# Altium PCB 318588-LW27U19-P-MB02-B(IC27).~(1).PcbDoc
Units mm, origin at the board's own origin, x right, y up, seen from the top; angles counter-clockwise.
Board outline 187.83 x 97.54 mm, 2 copper layers (Top Layer, Bottom Layer); 79 components, 53 nets, 224 pads, 27 vias.
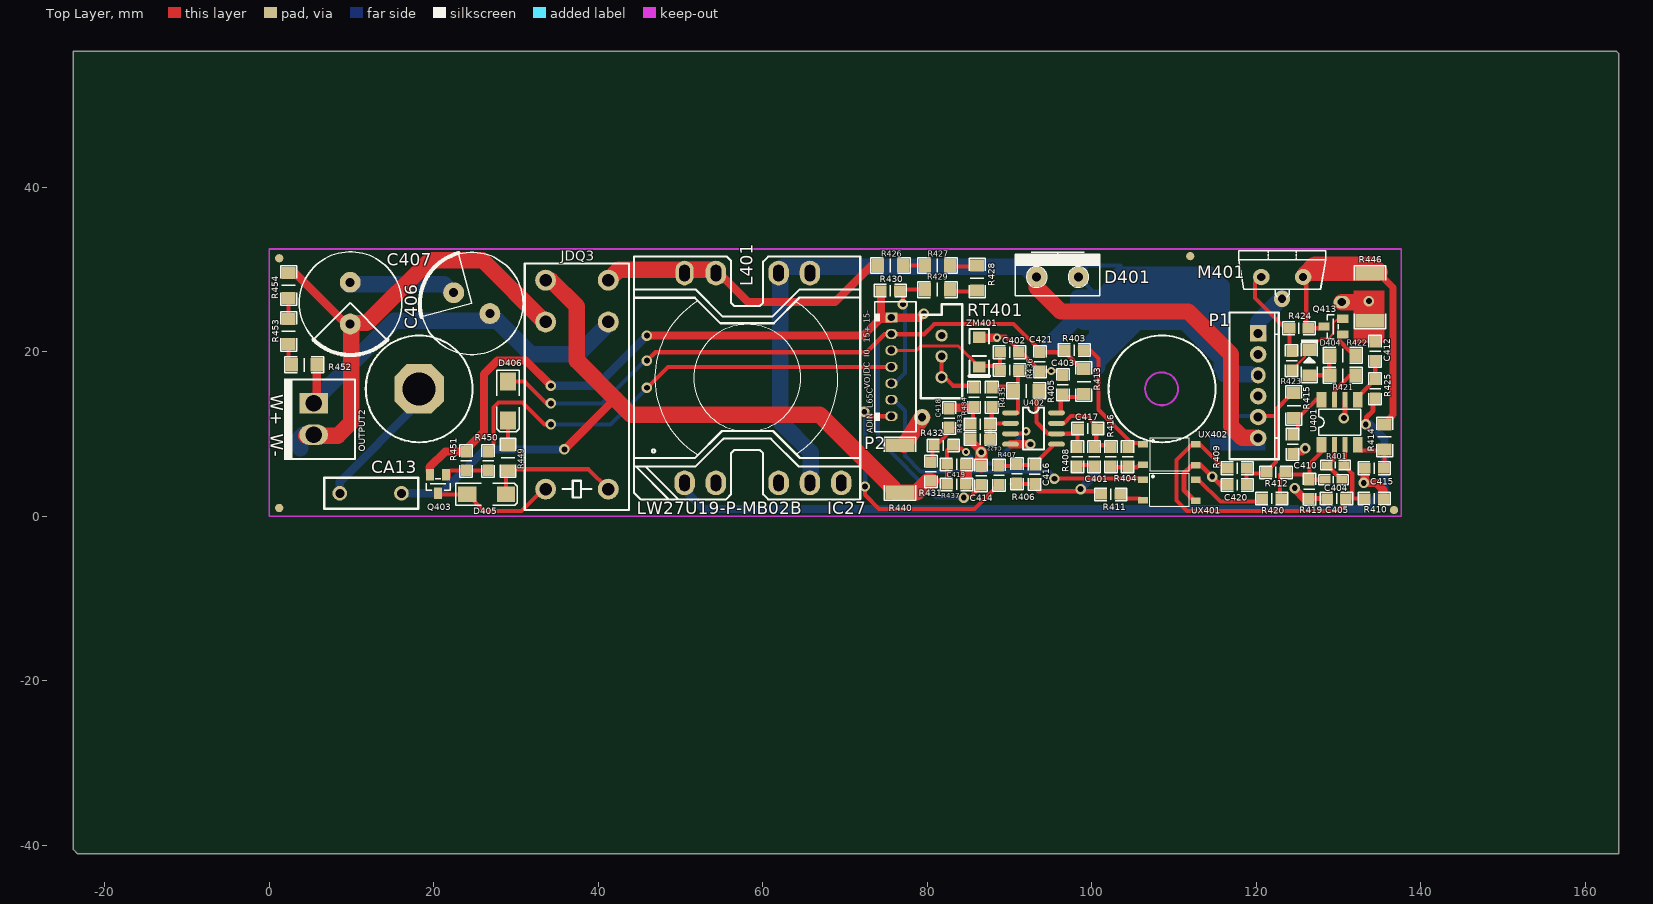
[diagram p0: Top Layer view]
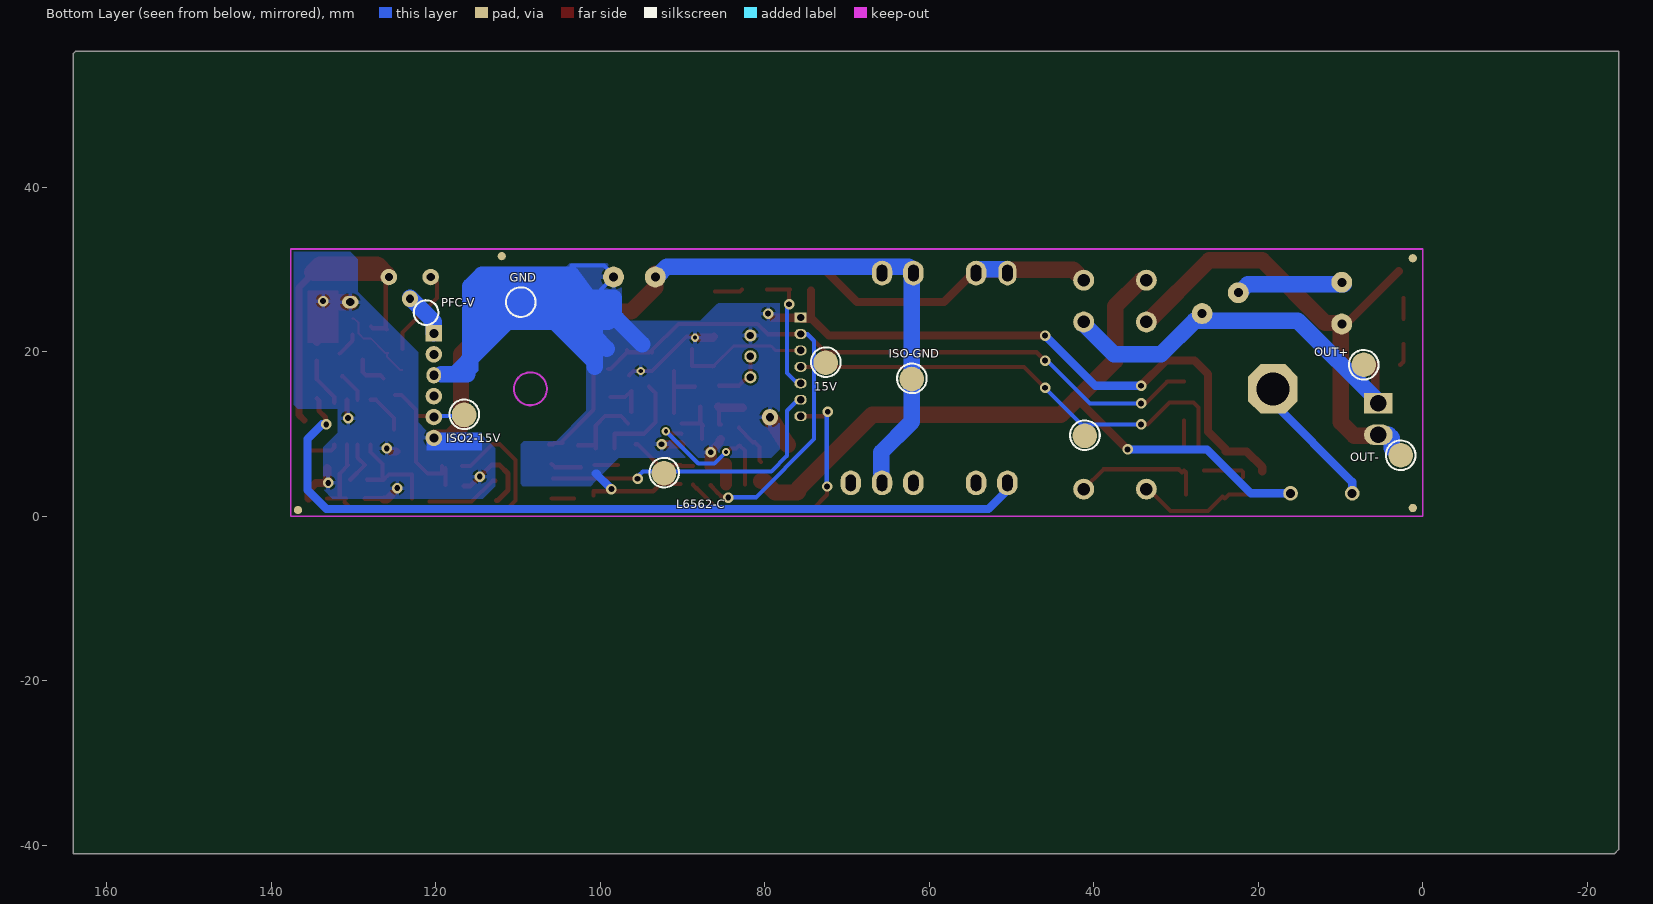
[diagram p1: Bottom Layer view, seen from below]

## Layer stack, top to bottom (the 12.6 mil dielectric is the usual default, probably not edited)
Top Solder: solder mask 0.0102, Solder Resist, Dk 3.5
Top Layer: signal copper 0.0356
Dielectric1: dielectric 0.32, FR-4, Dk 4.8
Bottom Layer: signal copper 0.0356
Bottom Solder: solder mask 0.0102, Solder Resist, Dk 3.5

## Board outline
-23.79,56.515 163.789,56.515 164.043,56.261 164.043,-41.021 -23.282,-41.021 -23.79,-40.513 -23.79,56.007

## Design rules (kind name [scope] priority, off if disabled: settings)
Clearance [All] p1: gap=0.254 ignorepadtopadclearanceinfootprint=FALSE
ComponentClearance [All] p1: gap=0 collisioncheckmode=3 verticalgap=0 showdistances=FALSE
HoleToHoleClearance [All] p1: gap=0 allowstackedmicrovias=TRUE
MinimumSolderMaskSliver [All] p1: minsoldermaskwidth=0
PolygonConnect [All] p1: connectstyle=Relief reliefconductorwidth=0.5 reliefentries=4 polygonreliefangle="90 Angle" airgapwidth=0.254
RoutingVias [All] p1: holewidth=0.711 width=1.27 viastyle="Through Hole" minholewidth=0.711 minwidth=1.27 maxholewidth=0.711 maxwidth=1.27
SilkToSilkClearance [All] p1: silktosilkclearance=0
SilkToSolderMaskClearance SilkscreenOverComponentPads [IsPad] p1: minsilkscreentomaskgap=0 clearancetoexposedcopper=TRUE
SolderMaskExpansion [All] p1: expansion=0.102 istentingtop=FALSE
Width [All] p1: maxlimit=5 minlimit=0.254 preferedwidth=0.254 minimp=50.000000 maximp=50.000000 favimp=50.000000
25 further rules are at their usual default settings.

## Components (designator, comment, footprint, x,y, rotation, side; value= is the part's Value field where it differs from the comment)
C401 "" RW0805 100.289,7.239 r0 top
C402 "0805" RW0805 90.002,19.939 r270 top
C403 "301008" RW0805 96.479,16.002 r0 top
C404 "" RW0603 130.388,4.445 r90 top
C405 "301008" RW0805 129.753,2.159 r270 top
C406 "450V47uF" CE12.5 22.438,27.178 r330 top
C407 "450V47uF" CE12.5 9.865,23.368 r90 top
C410 "301009" RW0805 124.419,8.763 r180 top
C412 "301001" RW0805 134.452,20.066 r0 top
C414 "301008" RW0805 86.563,4.953 r0 top
C415 "" RW0805 134.325,5.842 r90 top
C416 "301008" RW0805 93.066,5.105 r180 top
C417 "301008" RW0805 99.527,10.668 r270 top
C418 "0805" RW0805 82.677,11.938 r0 top
C419 "301008" RW0805 83.566,6.325 r270 top (schematic designator C414)
C420 "301013" RW0805 117.688,3.81 r90 top
C421 "301013" RW0805 93.685,18.796 r180 top
C422 "301008" RW0805 86.462,9.373 r270 top (schematic designator C414)
CA13 "102" Y2C 16.225,2.822 r270 top
D401 "308006" TO-220-KA 95.844,29.083 r0 top
D404 "307004" SOD-123 126.451,18.669 r0 top
D405 "M7" SMA 28.661,2.667 r180 top
D406 "M7" SMA 29.042,11.811 r90 top
JDQ3 "HF115F" RELAY-HF115F 41.234,3.302 r90 top locked
L401 "PQ26/25" T-PQ2625 55.368,15.538 r180 top
M401 "314012" TO220VS 120.609,29.083 r0 top
OUTPUT2 "322055" JST-3.96-2P 5.42,13.716 r270 top
P1 "Header 6" 6P插座 120.228,22.225 r270 top
P2 "Header 7" 2.0*7 75.651,24.161 r270 top
Q403 "2N3904" SOT-23-BEC 20.533,3.937 r180 top
Q413 "309005" SOT-23-BEC 129.372,23.063 r90 top
R401 "" RW0603 128.61,6.223 r270 top
R403 "" RW0805 97.876,20.193 r270 top
R404 "" RW0805 104.353,7.239 r180 top
R405 "" RW1206 93.558,15.24 r90 top
R406 "" RW0805 90.907,5.156 r0 top
R407 "303020" RW0805 88.722,5.004 r180 top
R408 "303046" RW0805 98.257,7.239 r0 top
R409 "" RW0805 117.688,5.842 r270 top
R410 "" RW0805 134.325,2.159 r90 top
R411 "" RW0805 102.321,2.667 r270 top
R412 "303053" RW0805 122.387,5.334 r270 top
R413 "303074" RW1206 99.019,14.859 r0 top
R414 "" RW1206 135.595,8.128 r0 top
R415 "303074" RW1206 124.546,11.938 r0 top
R416 "0805" RW0805 102.321,7.239 r0 top
R419 "" RW0805 126.451,3.302 r0 top
R420 "" RW0805 121.879,2.159 r270 top
R421 "303075" RW1206 128.991,17.145 r270 top
R422 "" RW1206 128.991,19.558 r270 top
R423 "303073" RW0805 124.292,18.923 r0 top
R424 "303043" RW0805 125.181,22.86 r90 top
R425 "303055" RW0805 134.452,15.494 r180 top
R426 "303094" RW1206 74,30.48 r270 top
R427 "303094" RW1206 79.715,30.48 r270 top
R428 "303094" RW1206 86.065,30.48 r180 top
R429 "303094" RW1206 82.763,27.559 r90 top
R430 "303033" RW0805 75.524,27.432 r270 top
R431 "0805" RW0805 80.442,5.436 r0 top
R432 "0805" RW0805 81.966,8.611 r270 top
R433 "0805" RW0805 86.446,11.176 r90 top
R434 "0805" RW0805 85.684,14.478 r0 top
R435 "0805" RW0805 87.843,14.478 r0 top
R436 "0805" RW0805 90.002,17.78 r90 top
R437 "0805" RW0805 83.566,3.886 r90 top (schematic designator R433)
R440 "" RW2512 76.683,8.661 r180 top
R446 "" RW2512 133.817,29.515 r180 top
R449 "1206" RW1206 29.042,8.636 r180 top
R450 "0805" RW0805 26.629,6.731 r180 top
R451 "0805" RW0805 23.962,6.731 r180 top
R452 "303094" RW1206 2.753,18.415 r270 top
R453 "303094" RW1206 2.372,24.003 r180 top
R454 "303094" RW1206 2.372,29.591 r180 top
RT401 "10K" 直插电位器 81.747,16.891 r90 top
U401 "311046" SO-8 130.134,11.43 r0 top
U402 "311026" SOP-8 90.129,12.573 r270 top
UX401 "317001" LTV 109.433,3.175 r270 top
UX402 "317001" LTV 109.433,7.493 r270 top
ZM401 "5.1V" 二极管 86.319,21.761 r270 top

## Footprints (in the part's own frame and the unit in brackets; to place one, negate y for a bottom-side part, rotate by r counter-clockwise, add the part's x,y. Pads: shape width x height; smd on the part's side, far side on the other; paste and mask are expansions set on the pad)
2.0*7 [mm]
  rect 1.2x1.5 hole 0.9: 1(0,0)
  oval 1.2x1.5 hole 0.9: 2(2,0) 3(4,0) 4(6,0) 5(8,0) 6(10,0) 7(12,0)
  silkscreen extent -1.9,-2.01 13.89,2.99
6P插座 [mm]
  rect 2x2 hole 1.1: 1(0,0)
  round 2 hole 1.1: 2(2.54,0) 4(7.62,0) 5(10.16,0) 6(12.7,0)
  oval 2x1.8 hole 1.1: 3(5.08,0)
  silkscreen extent -2.54,-3.5 15.29,2.5
CE12.5 [mil]
  round 100 hole 43: +(200,0) -(0,0)
  silkscreen extent -148,-246 346,244
JST-3.96-2P [mm]
  rect 2.5x3.5 hole 2: 1(0,0)
  oval 2.5x3.5 hole 2: 2(3.81,0)
  silkscreen extent -3.05,-3.59 6.86,5.02
LTV [mm]
  rect 0.8x1.2 smd: 1(-1.27,-3.2) 2(1.23,-3.2) 3(1.27,3.2) 4(-1.27,3.2)
  silkscreen extent -2.04,-2.4 1.96,2.4
RELAY-HF115F [mil]
  round 100 hole 60: 1(0,300) 2(0,0) 3(800,300) 4(800,0) 5(1000,300) 6(1000,0)
  silkscreen extent -100,-100 1080,400
RW0603 [mil]
  rect 35x50 smd: 1(0,0) 2(0,80)
  silkscreen extent -23,-30 23,110
RW0805 [mil]
  rect 50x55 smd: 1(0,-45) 2(0,45)
  silkscreen extent -30,-77 30,77
RW1206 [mil]
  rect 66x58 smd: 1(0,0) 2(0,120)
  silkscreen extent -38,-34 38,154
RW2512 [mil]
  rect 140x65 smd: 1(0,0) 2(0,227)
  silkscreen extent -76,-38 76,265
SMA [mil]
  rect 87x75 smd: A(180,0) K(-6,0)
  silkscreen extent -60,-53 234,53
SO-8 [mm]
  rect 1.2x1.905 smd: 1(-2.2,-2.731) 4(2.2,-2.731) 5(2.2,2.73) 8(-2.2,2.73)
  rect 0.61x1.905 smd: 2(-0.63,-2.73) 3(0.64,-2.731) 6(0.64,2.73) 7(-0.63,2.73)
  silkscreen extent -2.53,-1.56 2.55,1.59
SOD-123 [mil]
  rect 66x58 smd: A(0,-61) K(0,61)
  silkscreen extent -41,-95 41,110
SOP-8 [mil]
  oval 24x80 smd: 1(0,0) 2(50,0) 3(100,0) 4(150,0) 5(150,220) 6(100,220) 7(50,220) 8(0,220)
  silkscreen extent -25,60 175,160
SOT-23-BEC [mil]
  rect 40x55 smd: B(-38,-45) C(0,45) E(38,-45)
  silkscreen extent -58,-24 57,30
T-PQ2625 [mm]
  rect 0x0 all layers, no hole: 1(8.673,11.474)
  oval 2.5x3 hole 1.25 slot 2 at 90 deg: 2(4.863,11.474) 3(1.053,11.474) 4(-6.567,11.474) 5(-10.377,11.474) 6(-14.187,11.474)
  round 0 all layers, no hole: 7(-14.187,-14.027) 12(8.673,-14.026)
  oval 2.5x3 hole 1.3 slot 2 at 90 deg: 8(-10.377,-14.027) 9(-6.567,-14.027) 10(1.053,-14.027)
  oval 2.2x3 hole 1.3 slot 2 at 90 deg: 11(4.863,-14.027)
  silkscreen extent -16.49,-16.03 11.01,13.47
TO220VS [mm]
  round 2 hole 1: 1(0,0) 2(2.517,-2.646) 3(5.08,0)
  silkscreen extent -2.75,-2.42 7.83,3.17
TO-220-KA [mil]
  round 100 hole 43: A(100,0) K(-100,0)
  silkscreen extent -202,-90 202,118
Y2C [mil]
  round 70 hole 43.31: 1(1.09,-5.11) 2(1.09,-300.38)
  silkscreen extent -74,-375 76,75
二极管 [mm]
  rect 1.35x1.5 smd: 1(0,0) 2(3.6,0)
  silkscreen extent -1.02,-1.2 4.7,1.2
直插电位器 [mm]
  round 1.5 hole 0.9: 1(0.008,0.006) 2(2.548,0.006) 3(5.088,0.006)
  silkscreen extent -2.53,-2.53 8.9,2.55

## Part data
C401 C403 C404 C405 C414 C416 C417 C419 C422: library part CAP, "贴片?"
C402 C418: library part C
C406 C407: library part "Cap Pol2", "Polarized Capacitor"
C410 C412 C415 C420 C421: library part C, "贴片?"
CA13: library part CAP, "Cap"
D401: library part "Diode 1N914", "直插二"
D404: library part DIO
JDQ3: library part "Relay - 两组常开", "Dual-Pole Single-"
L401: library part indu
M401: library part MOSFET-N, "TO2"
OUTPUT2: library part "Header 2", "接线?"
P1: "Header, 6-Pi"
P2: "Header,"
Q403: library part NPN, "NPN Bipolar Tra"
Q413: library part PNP
R401 R403 R404 R405 R406 R407 R408 R409 R410 R411 R412 R413 R414 R415 R419 R420 R421 R422 R423 R424 R425 R426 R427 R428 R429 R430 R440 R446 R452 R453 R454: library part Res2, "贴片?"
R416 R431 R432 R433 R434 R435 R436 R437 R449 R450 R451: library part Res2, "Resistor"
U401: library part L6562, "贴片"
U402: library part LM393
UX401 UX402: library part Optoisolator1

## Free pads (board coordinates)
  round 1 all layers, no hole: 0(1.229,1.016) 0(1.229,31.369) 0(111.973,31.623) 0(136.738,0.762)
  round 3 on Bottom Solder: 0(2.703,7.416) 0(7.198,18.415) 0(41.107,9.779) 0(62.139,16.687) 0(72.603,18.669) 0(92.253,5.232) 0(109.737,26.062) 0(116.545,12.319) 0(121.194,24.688)
  round 3 smd far side: 0(2.703,7.416) 0(7.198,18.415) 0(41.107,9.779) 0(62.139,16.687) 0(72.603,18.669) 0(92.253,5.232) 0(116.545,12.319)
  oct 6x6 hole 4: 0(18.247,15.494)
  round 2 hole 1: 2(79.375,12.04)
  oval 2x1.524 hole 1: 3(130.388,26.035)

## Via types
v1: diameter 1.27, hole 0.711, Top Layer to Bottom Layer, 23 vias
v2: diameter 1, hole 0.5, Top Layer to Bottom Layer, 4 vias

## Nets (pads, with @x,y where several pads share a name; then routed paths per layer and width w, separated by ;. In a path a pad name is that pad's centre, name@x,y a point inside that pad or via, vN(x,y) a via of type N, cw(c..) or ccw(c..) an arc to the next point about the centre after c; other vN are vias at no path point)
15V: C414.1 C421.1 D406.A P2.2 pad.0@72.603,18.669 R403.1 R413.2 | length 107.5
  Top Layer w0.5: D406.A 31.074,16.383 33.741,13.716 v1(34.249,13.716) ; v1(45.933,18.923) 46.949,19.939 72.603,19.939 74.793,22.129 79.619,22.129 80.858,23.368 90.51,23.368 93.685,20.193 C421.1 ; v1(84.448,2.268) 84.595,2.415 85.285,2.415 85.911,3.042 85.911,3.095 86.563,3.746 C414.1 ; C421.1@94.066,19.939 R403.1@96.733,19.939 ; R403.1 R403.1@96.733,19.939 ; R413.2 98.765,17.907 R403.1@96.733,19.939
  Bottom Layer w0.5: v1(34.249,13.716) 40.472,13.716 45.679,18.923 v1(45.933,18.923) ; P2.2@75.651,22.129 74.793,22.129 74,21.336 74,9.398 81.087,2.311 84.405,2.311 v1(84.448,2.268)
ADIN2: P2.7 R407.2 | length 32
  Top Layer w0.508: v1(72.349,12.7) 72.888,12.161 P2.7 ; v1(72.418,3.625) 72.418,2.618 74.147,0.889 85.75,0.889 88.278,3.416 88.341,3.416 88.722,3.797 R407.2
  Bottom Layer w0.508: v1(72.349,12.7) 72.476,12.573 72.476,3.683 v1(72.418,3.625)
EARTH: CA13.2 pad.0@18.247,15.494 | length 15.6
  Bottom Layer w1: CA13.2 8.595,4.191 pad.0@18.12,13.716
  Bottom Layer w2: pad.0@17.358,13.716 pad.0@18.12,13.716
GND: C402.2 C403.2 C414.2 C416.2 C419.2 C421.2 C422.1 D401.A P1.3 P2.1 pad.2 Q403.E R406.1 R411.1 R430.1 R437.1 R440.1 R451.1 RT401.3 U402.4 ZM401.1 | length 255.7
  Top Layer w0.5: ZM401.1@86.192,21.844 89.494,21.844 C421.2 v2(95.082,17.653) 95.971,17.653 C403.2 ; 90.256,3.937 92.669,3.937 93.558,3.048 100.797,3.048 R411.1@100.797,2.54 ; U402.4@90.383,8.763 U402.4@91.018,8.763
  Top Layer w1: Q403.E@19.517,5.486 19.517,5.969 21.422,7.874 R451.1 23.962,8.128 26.121,10.287 26.121,17.272 27.772,18.923 31.201,18.923 v1(34.249,15.875) ; v1(45.933,21.971) 72.222,21.971 74.254,24.003 ; R430.1 74.381,24.13 74.254,24.003 ; P2.1@75.524,24.003 74.254,24.003 ; P2.1@75.651,24.129 79.079,24.129 v1(79.588,24.638) ; C422.1 85.382,9.373 85.517,9.238 85.517,8.946 86.512,7.951 86.512,7.846 v1(86.563,7.794) ; ZM401.1@86.192,21.844 86.319,21.717 v2(88.478,21.717) ; U402.4 v1(92.542,8.763)
  Top Layer w1.5: R437.1 C419.2 86.335,6.325 C414.2 v1(86.563,7.794)
  Top Layer w2: R440.1@77.175,8.687 77.226,8.687 pad.2
  Bottom Layer w0.5: D401.A@98.384,29.464 98.511,29.464 99.527,30.48 103.464,30.48 ; D401.A@98.892,28.575 99.908,27.559 ; 115.021,19.304 115.021,17.78 116.164,16.637
  Bottom Layer w1: v1(34.249,15.875) 39.837,15.875 v1(45.933,21.971) ; v1(98.638,3.302) 100.543,5.207 100.416,5.207 ; 101.432,18.796 105.559,22.924
  Bottom Layer w2: 94.9,20.9 97.953,23.953 ; 98.561,25.35 100.289,23.622 ; 98.892,25.527 109.941,25.527 ; 99.196,20.37 100.67,21.844 ; 100.67,18.161 100.67,21.844 ; 100.924,20.193 104.353,23.622 ; 102.249,23.423 100.67,21.844 ; 102.956,27.432 108.544,27.432 ; 104.48,23.749 104.353,23.622 ; 109.814,25.654 109.941,25.527 ; 110.322,27.559 113.37,27.559 114.132,26.797 114.132,24.13 ; 111.393,24.075 109.941,25.527 ; 112.608,25.4 112.608,27.051 ; 115.783,21.336 115.783,27.94 114.386,29.337 107.528,29.337 ; 116.164,17.272 117.688,17.272 ; 116.164,17.78 116.164,18.796 ; P1.3@119.339,17.272 117.688,17.272 ; 100.289,23.622 104.353,23.622 ; 100.289,23.622 100.67,23.241 100.67,21.844 ; 100.289,23.622 99.019,23.622 98.384,24.257 98.384,26.543 101.368,26.543 103.464,29.337 107.528,29.337 ; 104.353,23.622 111.338,23.622 115.783,19.177 ; 107.528,29.337 115.783,21.082 115.783,19.177 ; 115.783,19.177 116.164,18.796 ; 116.164,18.796 117.688,17.272
I_OUT2: C402.1 P2.3 R436.2 ZM401.2 | length 16.6
  Top Layer w0.4: P2.3 78.699,20.161 79.239,20.701 83.779,20.701 86.192,18.288 ZM401.2
  Top Layer w0.5: ZM401.2@86.192,18.288 88.859,18.288 C402.1 C402.1@88.859,20.32
ISO2-15V: C420.1 P1.5 pad.0@116.545,12.319 R409.2 R412.1 R415.2 | length 21.3
  Top Layer w0.5: C420.1 R409.2 ; R409.2@119.212,6.096 119.212,5.207 120.99,5.207 122.387,6.604 122.387,12.192 ; P1.5@120.228,12.192 122.387,12.192 ; R415.2@124.927,14.732 124.165,14.732 122.387,12.954 122.387,12.192
  Bottom Layer w0.5: pad.0@116.545,12.319 116.672,12.192 P1.5@119.339,12.192
ISO2-GND: C405.1 C410.2 C412.2 C415.2 C420.2 D401.K L401.5 L401.8 L401.9 P1.6 pad.0@62.139,16.687 pad.3 R410.1 R419.1 R446.2 U401.6 UX401.3 UX402.3 | length 128.5
  Top Layer w0.6: UX401.3 112.481,1.905 111.211,3.175 111.211,5.207 112.227,6.223 UX402.3 113.243,6.223 v1(114.64,4.826) 115.783,3.683 C420.2@116.545,3.683 ; R419.1@126.197,2.159 R419.1 C405.1 ; v1(130.642,11.938) 130.774,12.07 U401.6
  Top Layer w1: v1(124.673,3.429) 124.673,3.302 125.943,2.032 R419.1@126.324,2.032 ; C410.2@124.8,7.874 125.562,7.874 v1(125.943,8.255) ; C415.2 133.182,4.191 v1(133.055,4.064) 134.579,4.064 135.468,3.175 R410.1 ; R446.2@133.563,23.749 134.452,22.86 C412.2
  Top Layer w2: D401.K@93.304,29.464 D401.K 93.304,27.813 96.225,24.892 111.719,24.892 116.926,19.685 116.926,10.922 118.323,9.525 P1.6@120.101,9.525 ; pad.3 132.42,26.035
  Bottom Layer w2: L401.5@65.835,5.29 65.835,7.784 62.152,11.467 62.152,30.029 62.476,30.353 91.907,30.353 D401.K@92.986,29.273
  other v1: 133.69,26.162
JDQ2-C: P2.4 pad.0@41.107,9.779 R450.1 | length 58.2
  Top Layer w0.5: R450.1 27.264,8.509 27.264,13.208 27.899,13.843 30.82,13.843 33.487,11.176 v1(34.249,11.176) ; v1(45.933,15.621) 48.473,18.161 P2.4
  Bottom Layer w0.5: v1(34.249,11.176) 41.488,11.176 v1(45.933,15.621)
L6562-2C: P2.6 pad.0@92.253,5.232 UX401.1 | length 36.8
  Top Layer w0.5: v1@95.59,4.318 95.844,4.572 UX401.1@105.725,4.572
  Bottom Layer w0.5: P2.6@75.809,14.32 77.302,12.827 77.302,7.366 79.207,5.461 94.828,5.461 v1@95.272,5.016
  other v1: 95.463,4.572
NetC401_1: C401.1 R408.1 | length 2.8
  Top Layer w0.5: R408.1@97.876,6.223 C401.1@100.67,6.223
NetC401_2: C401.2 C417.2 R416.2 U402.7 | length 9.7
  Top Layer w0.5: U402.7@96.606,11.303 97.495,12.192 99.4,12.192 100.543,11.049 C401.2@100.543,8.636 ; C401.2@100.543,8.255 C401.2@100.543,8.636 ; R416.2@102.702,8.636 C401.2@100.543,8.636
NetC403_1: C403.1 R413.1 U402.8 | length 5.4
  Top Layer w0.5: U402.8@96.225,12.7 96.225,15.24 96.987,14.478 R413.1@98.765,14.478
NetC404_1: C404.1 R401.1 U401.2 | length 5.4
  Top Layer w0.5: U401.2 129.504,7.117 R401.1 C404.1
NetC404_2: C404.2 R412.2 R419.2 R420.2 U401.1 | length 13.6
  Top Layer w0.5: R420.2@122.895,2.159 122.895,5.08 125.689,5.08 R419.2@126.197,4.572 ; U401.1 127.934,7.833 126.451,6.35 126.451,4.572 R419.2@126.197,4.572 ; C404.2 R419.2 126.324,4.445 R419.2@126.197,4.572
NetC405_2: C405.2 R401.2 R409.1 R410.2 U401.3 UX402.4 | length 44.2
  Top Layer w0.5: R409.1@116.799,6.096 115.783,6.096 113.116,8.763 UX402.4 112.227,8.763 110.322,6.858 110.322,1.905 111.596,0.631 130.003,0.631 C405.2@131.086,1.714 ; U401.3 130.774,6.355 R401.2 131.658,5.207 131.658,2.286 ; C405.2 R410.2
NetC406_+: C406.+ JDQ3.4 OUTPUT2.1 pad.0@7.198,18.415 R452.2 | length 48.1
  Top Layer w1: OUTPUT2.1 5.801,14.097 R452.2
  Bottom Layer w2: OUTPUT2.1@5.483,14.034 15.199,23.749 27.772,23.749 31.836,19.685 37.551,19.685 41.234,23.368 JDQ3.4
NetC406_-: C406.- C407.+ | length 13.1
  Bottom Layer w2: C407.+@9.611,28.194 21.295,28.194 C406.-@22.311,27.178
NetC407_-: C407.- JDQ3.3 OUTPUT2.2 pad.0@2.703,7.416 R454.1 | length 60.8
  Top Layer w1: R454.1@2.943,29.781 9.23,23.495 9.865,23.495 C407.-
  Top Layer w2: OUTPUT2.2@4.531,9.779 8.341,9.779 9.992,11.43 C407.-@9.992,23.368 ; C407.-@9.865,23.495 11.897,23.495 19.533,31.131 25.978,31.131 33.487,23.622 JDQ3.3
  Bottom Layer w2: pad.0@3.762,8.255 3.762,9.518 4.15,9.906 OUTPUT2.2
NetC410_1: C410.1 R415.1 U401.8 | length 5.2
  Top Layer w0.5: 125.054,10.541 125.054,11.938 127.276,14.16 U401.8
NetC412_1: C412.1 R425.1 U401.5 | length 5.9
  Top Layer w0.5: U401.5@132.334,13.802 U401.5@132.334,14.034 ; U401.5 132.334,14.519 R425.1 C412.1
NetC415_1: C415.1 R414.1 U401.4 | length 6.3
  Top Layer w0.5: U401.4 132.334,8.341 132.674,8.001 135.595,8.001 C415.1@135.595,5.461
NetC416_1: C416.1 R406.2 R407.1 U402.5 | length 8.1
  Top Layer w0.5: R407.1@88.722,6.096 90.129,6.096 90.256,6.223 92.669,6.223 92.923,6.223 95.463,8.763 U402.5
NetC417_1: C417.1 R405.1 R408.2 U402.6 | length 11.9
  Top Layer w0.5: R405.1@94.066,15.748 R405.1 93.304,14.986 93.304,11.43 94.701,10.033 98.257,10.033 R408.2 R408.2@98.257,8.255
NetC418_1: C418.1 R431.2 R432.1 | length 5.5
  Top Layer w0.5: R431.2 80.632,6.769 80.632,8.42 R432.1 81.208,8.996 81.408,8.996 83.144,10.731 C418.1@83.144,10.795
NetC418_2: C418.2 R433.2 R434.1 | length 5.7
  Top Layer w0.5: R433.2 85.557,11.176 85.557,13.208 R434.1@85.557,13.589
  Top Layer w1: C418.2@82.677,13.208 85.557,13.208 R434.1
NetD404_A: D404.A R421.1 R422.1 | length 4.4
  Top Layer w0.5: D404.A@126.324,16.739 126.73,17.145 128.483,17.145 128.864,17.526 R422.1@128.864,19.05
NetD404_K: D404.K Q413.E R423.1 | length 9.7
  Top Layer w0.254: R423.1@124.038,17.78 R423.1 125.943,19.431 D404.K@125.943,19.685 ; D404.K@125.714,19.837 126.095,19.837 127.848,21.59 128.737,21.59 129.372,22.225 129.372,23.495 129.905,24.028 Q413.E@130.134,24.028
NetD405_A: D405.A JDQ3.1 Q403.C | length 15.1
  Top Layer w0.5: Q403.C@20.457,2.667 23.581,2.667 D405.A@24.089,2.159 ; D405.A@24.343,2.413 26.121,0.635 30.693,0.635 JDQ3.1@33.614,3.556
NetD405_K: D405.K JDQ3.2 R449.2 | length 16.1
  Top Layer w0.5: D405.K 28.813,5.359 R449.2 ; R449.2@29.296,5.334 29.677,5.715 38.821,5.715 JDQ3.2
NetD406_K: D406.K R449.1 | length 3
  Top Layer w0.5: R449.1 D406.K
NetL401_2: L401.2 R425.2 | length 101
  Top Layer w0.6: v1@133.055,11.176 133.372,11.493 133.372,12.002 134.198,12.827 134.198,14.097 R425.2
  Bottom Layer w1: L401.2@50.722,4.274 50.722,2.958 52.799,0.881 83.871,0.881 83.873,0.879 85.023,0.879 85.025,0.881 133.301,0.881 135.595,3.175 135.595,9.398 133.817,11.176 v1(133.309,11.176)
NetM401_1: M401.1 R423.2 R424.2 | length 11.3
  Top Layer w0.5: M401.1@120.609,29.591 120.609,29.21 119.847,28.448 119.847,26.543 124.038,22.352 R423.2@124.038,20.32
NetM401_3: M401.3 Q413.C R414.2 R424.1 R446.1 | length 46.7
  Top Layer w0.5: M401.3@125.498,29.781 126.07,29.21 R424.1@126.07,23.063 ; R424.1@125.943,22.733 126.07,22.86 R424.1 127.645,22.86 Q413.C@127.848,23.063
  Top Layer w0.8: R446.1@134.325,29.083 135.341,29.083 136.611,27.813 136.611,12.319 R414.2@135.976,11.684
  Top Layer w2: M401.3@125.943,29.464 127.086,30.607 134.071,30.607 R446.1@135.023,29.654 ; M401.3@126.324,29.591 R446.1@134.833,29.591
NetQ403_B: Q403.B R450.2 R451.2 | length 5.5
  Top Layer w0.5: Q403.B@21.866,4.763 21.866,5.397 22.057,5.588 R450.2
NetQ413_B: Q413.B R422.2 | length 2.9
  Top Layer w0.5: Q413.B@130.134,22.098 130.134,21.336 R422.2@131.658,19.812
NetR403_2: R403.2 R404.1 UX402.1 | length 15.7
  Top Layer w0.5: R403.2 99.781,20.193 100.797,19.177 100.797,12.954 104.607,9.144 104.607,8.89 105.598,8.89 105.725,8.763 UX402.1
NetR404_2: R404.2 R416.1 UX402.2 | length 3.7
  Top Layer w0.5: R416.1@102.321,5.969 105.511,5.969 UX402.2@105.892,6.35
NetR405_2: R405.2 R435.2 R436.1 U402.1 | length 7.6
  Top Layer w0.5: 88.478,15.748 R405.2@91.018,15.748 ; U402.1@91.018,12.573 R405.2@91.018,15.748 ; R436.1@91.018,17.653 R405.2@91.018,15.748
NetR411_2: R411.2 UX401.2 | length 2.7
  Top Layer w0.5: R411.2@103.21,2.159 UX401.2@105.892,2.159
NetR420_1: R420.1 UX401.4 | length 9.1
  Top Layer w0.5: UX401.4@112.735,4.318 113.116,4.318 115.656,1.778 R420.1@120.736,1.778
NetR421_2: R421.2 U401.7 | length 3.7
  Top Layer w0.5: U401.7 129.504,15.245 131.277,17.018 R421.2@131.404,17.018
NetR426_2: R426.2 R427.1 | length 2.7
  Top Layer w0.5: R426.2 R427.1
NetR427_2: R427.2 R428.1 | length 3.4
  Top Layer w0.5: R427.2 82.89,30.353 R428.1@86.065,30.353
NetR428_2: R428.2 R429.1 | length 3.4
  Top Layer w0.5: R429.1 83.017,27.305 R428.2@86.065,27.305
NetR432_2: C419.1 R432.2 R437.2 U402.3 | length 18.5
  Top Layer w0.5: R437.2 C419.1 82.423,7.988 83.045,8.611 R432.2 83.494,8.226 84.177,8.226 84.574,7.829 v2(84.709,7.829) ; U402.3 90.15,10.054 91.532,10.054 91.816,10.338 v2(92.024,10.338)
  Bottom Layer w0.5: v2(84.709,7.829) 86.137,6.401 88.087,6.401 v2(92.024,10.338)
NetR433_1: C422.2 R433.1 R435.1 U402.2 | length 6.5
  Top Layer w0.5: R433.1@87.534,10.982 87.608,10.907 C422.2@87.608,9.376 ; R435.1@87.847,13.331 87.847,11.434 R433.1 87.716,11.303 U402.2
NetR434_2: R434.2 RT401.1 RT401.2 | length 6.9
  Top Layer w0.5: RT401.1@81.741,17.153 RT401.1@81.741,17.278 ; RT401.2@81.741,19.693 RT401.2 RT401.1@81.741,17.278 ; R434.2@85.557,15.875 83.144,15.875 RT401.1@81.741,17.278
NetR452_1: R452.1 R453.2 | length 2.7
  Top Layer w0.508: R453.2 2.372,18.796 R452.1
NetR453_1: R453.1 R454.2 | length 2.5
  Top Layer w0.508: R453.1 R454.2
PFC_V: M401.2 P1.1 | length 5.5
  Bottom Layer w2: P1.1 120.228,23.666 M401.2@123.126,26.564
V_OUT2: P2.5 R429.2 R430.2 | length 15.2
  Top Layer w0.5: v1@77.048,25.654 v1(77.048,25.781) 77.048,27.432 76.921,27.559 R429.2
  Bottom Layer w0.5: P2.5@75.651,16.129 76.032,16.129 77.302,17.399 v1@77.302,25.654
WLED+: JDQ3.6 L401.10 L401.11 R426.1 | length 40.6
  Top Layer w1: L401.10@54.315,29.947 58.227,26.035 68.793,26.035 73.238,30.48 R426.1
  Top Layer w2: JDQ3.6 42.479,29.947 L401.10@54.315,29.947
  Bottom Layer w2: L401.11@50.468,30.029 L401.10@54.278,30.029
WLED-: CA13.1 JDQ3.5 R431.1 R440.2 | length 92.9
  Top Layer w1: v1(35.9,8.128) 42.059,14.287
  Top Layer w2: JDQ3.5 34.249,28.702 37.424,25.527 37.424,18.923 42.059,14.287 44.028,12.319 66.954,12.319 75.905,3.369 75.905,3.07 76.079,2.896 78.715,2.896 80.112,4.293 R431.1
  Bottom Layer w1: CA13.1 20.914,2.794 26.248,8.128 v1(35.9,8.128)
pads on no net: L401.1 L401.3 L401.4 L401.6 L401.7 L401.12 P1.2 P1.4

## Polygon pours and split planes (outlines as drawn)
GND on Bottom Layer "Top Layer-No Net" (solid, remove dead copper, pour order 4): 78.191,25.908 78.191,8.128 79.207,7.112 97.749,7.112 100.67,4.191 101.178,3.683 109.433,3.683 109.687,3.937 109.687,5.969 109.687,8.763 109.56,8.89 109.306,9.144 106.131,9.144 105.369,9.144 101.686,12.827 101.686,17.907 101.686,20.828 99.654,22.86 98.765,23.749 92.796,23.749 87.843,23.749 85.811,25.781 85.684,25.908 78.191,25.908
ISO2-GND on Bottom Layer "ISO2-GND" (solid, remove dead copper, pour order 8): 114.386,9.906 112.735,8.255 112.735,5.08 112.735,3.683 114.259,2.159 132.547,2.159 133.69,3.302 133.69,8.382 132.166,9.906 131.912,10.16 131.912,13.081 134.198,13.081 136.738,13.081 137.5,13.843 137.5,32.004 136.992,32.512 130.769,32.512 129.499,31.242 129.499,27.305 124.927,22.733 122.133,19.939 122.133,14.859 122.133,11.43 120.736,10.033 120.482,9.779 118.45,9.779
GND on Bottom Layer "GND" (solid, remove dead copper, pour order 12): 97.368,26.543 97.368,28.956 99.146,30.734 103.718,30.734 104.353,30.099 104.353,28.575 102.321,26.543

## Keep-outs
Keep-Out Layer:
  circle w0.254: c108.489,15.494 r2
  lines w0.2: 0,0 137.6,0 137.6,32.5 0,32.5 0,0
  text "LW27U19-P-MB02B(IC27)" at 32.334,-18.212 h4

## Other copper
Top Layer:
  rectangle net ISO2-GND: 131.785,21.082 135.595,27.432
Bottom Layer:
  rectangle net ISO2-GND: 114.386,8.001 121.117,10.16

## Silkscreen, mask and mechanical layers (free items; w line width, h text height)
Top Overlay:
  circle w0.254: c108.544,15.494 r6.5
  circle w0.254: c18.247,15.494 r6.5
  text "15-" at 72.984,23.495 h0.7 r90
  text "15+" at 72.984,21.082 h0.7 r90
  text "I0" at 72.984,19.304 h0.7 r90
  text "JDC" at 72.984,17.018 h0.7 r90
  text "VO" at 73.05,15.494 h0.7 r90
  text "W+" at 0.213,14.859 h1.5 r270
  text "L65C" at 73.381,13.132 h0.7 r90
  text "ADIN" at 73.39,10.109 h0.7 r90
  text "W-" at 0.213,10.033 h1.5 r270
  text "LW27U19-P-MB02B" at 44.663,0.254 h1.5
  text "IC27" at 67.869,0.254 h1.5
Bottom Overlay:
  circle w0.254: c92.228,5.307 r1.8
  circle w0.254: c2.703,7.416 r1.8
  circle w0.254: c7.198,18.415 r1.8
  circle w0.254: c62.114,16.762 r1.8
  circle w0.254: c116.52,12.394 r1.8
  circle w0.254: c41.082,9.854 r1.8
  circle w0.254: c72.578,18.744 r1.8
  circle w0.254: c121.169,24.763 r1.5
  circle w0.254: c109.662,26.037 r1.8
  text "GND" at 110.998,28.524 h1
  text "PFC-V" at 119.329,25.502 h1
  text "OUT+" at 13.208,19.431 h1
  text "ISO-GND" at 64.922,19.253 h1
  text "15V" at 74,15.24 h1
  text "ISO2-15V" at 118.694,9.017 h1
  text "OUT-" at 8.814,6.68 h1
  text "L6562-C" at 90.78,0.991 h1

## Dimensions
137.6,0 to 0,0 on Keep-Out Layer
0,0 to 0,32.5 on Keep-Out Layer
